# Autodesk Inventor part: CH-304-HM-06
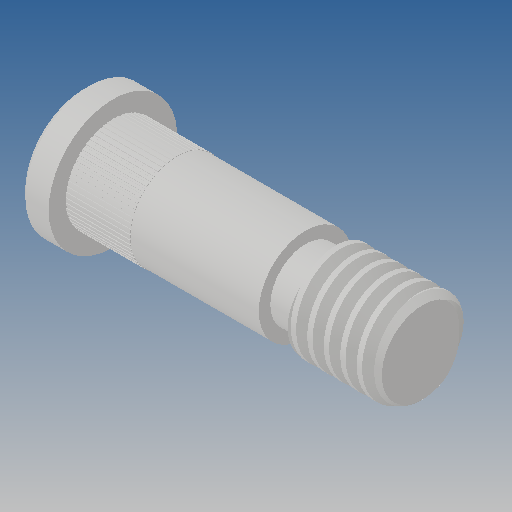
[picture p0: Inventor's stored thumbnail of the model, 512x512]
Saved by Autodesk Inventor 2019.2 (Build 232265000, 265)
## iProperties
Created: 2015-08
Part Number: CH-304-HM-06
Material: Ogólny
Document SubType Name: Modeling
Designer: CADENGINEERING4
Density: 1 g/cm^3
Appearance: Domyślna
Author: CADENGINEERING4
Revision Number: ÈÎºÎ
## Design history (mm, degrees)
feature "ÇÐ³ý-É¨Ãè2"
node "Bryła1"
